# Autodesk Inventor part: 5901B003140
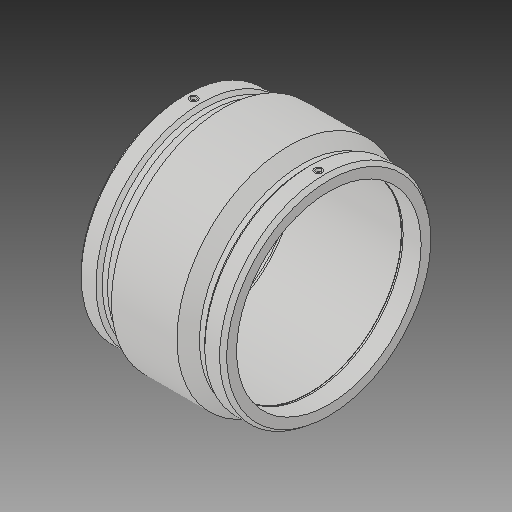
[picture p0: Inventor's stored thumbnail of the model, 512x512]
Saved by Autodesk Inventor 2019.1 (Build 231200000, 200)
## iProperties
Created: 2017-06
Part Number: 5901B003140
Material: Generic
Description: PLASSON IPS COUPLER 14''
Document SubType Name: Modeling
Designer: KIM
Mass: 8622.19 g
Surface Area: 6772.47 cm^2
Volume: 8622.19 cm^3
Density: 1 g/cm^3
Appearance: Default
Author: KIM
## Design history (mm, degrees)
derived "5901B.ipt"
feature "Solid1::5901B.ipt"
tag "TaggingFeature1"
body "Solid1"
other parameters: "d0" = 279.4, "d1" = 354, "d2" = 429.26, "d3" = 139.954, "d4" = 69.85, "d5" = 386.334, "d6" = 283.2, "d7" = 354, "d8" = 168 deg, "d10" = 55.9816, "d11" = 18.66053, "d13" = 279.4, "d14" = 17.6296, "d18" = 354, "d19" = 3.52592, "d20" = 168 deg, "d22" = 403.5044, "d23" = 429.26, "d24" = 391.39927, "d25" = 135 deg, "d26" = 125.73, "d27" = 135 deg, "d29" = 201.93, "d30" = 15, "d31" = 97.79, "d34" = 5 deg, "d35" = 15, "d39" = 5 deg, "d41" = 4, "d42" = 14, "d43" = 0, "d45" = 4, "d46" = 14, "d47" = 0, "d48" = 3, "d49" = 0, "d50" = 3, "d51" = 0, "d52" = 40.58666, "d53" = 10.14666, "d55" = 139.954, "d_" = 354, "L_" = 279.4, "L_1" = 139.954, "D_" = 429.26, "A_" = 201.93, "d_2" = 12, "B_" = 201.93
